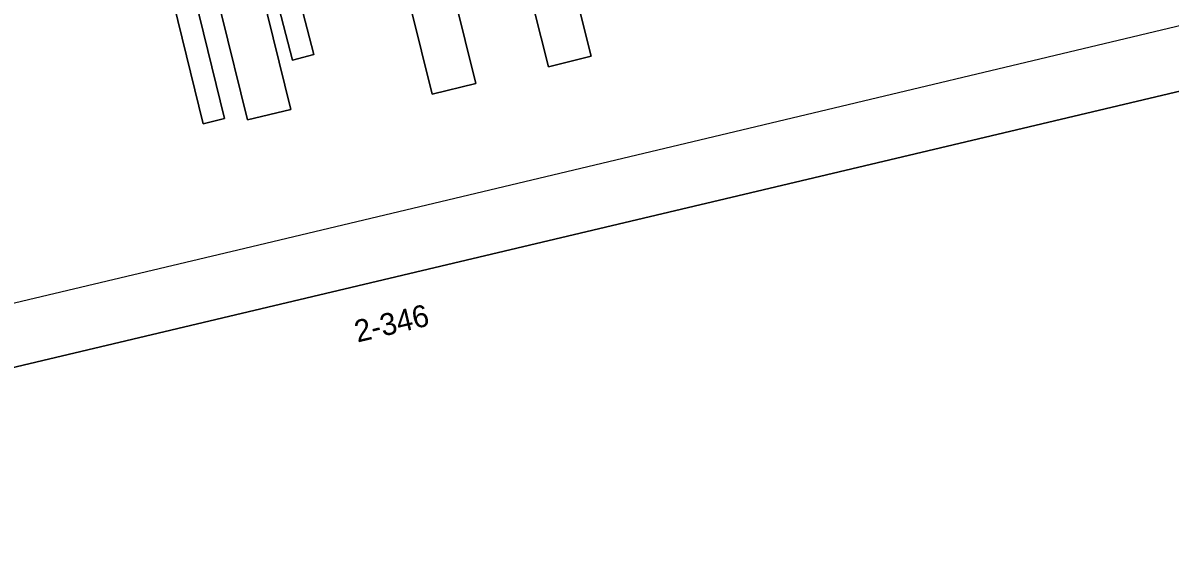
# Model space of a CAD drawing. Extents: x 160675 to 161153, y 383241 to 383714.
# Drawn here: x 161053 to 161105.1, y 383500.1 to 383524.5 of the extents above; entities that cross this region are included whole.
import ezdxf

# ---------------------------------------------------------------- set-up
doc = ezdxf.new("R2010")
doc.units = 0
for name, color, linetype in [('IMGEO_Erf', 7, 'Continuous'), ('IMGEO_Grasland_overig', 7, 'Continuous'), ('IMGEO_Lijnafwatering', 7, 'Continuous'), ('IMGEO_Pand', 7, 'Continuous'), ('IMGEO_Pand_nummerreeks', 7, 'Continuous')]:
    doc.layers.add(name, color=color, linetype=linetype)

msp = doc.modelspace()

# ---------------------------------------------------------------- linework, layer by layer
at = {"layer": 'IMGEO_Erf'}
msp.add_lwpolyline([(161052.435, 383508.826), (161071.419, 383513.322), (161096.427, 383519.245), (161115.421, 383523.744), (161114.881, 383526.021), (161118.321, 383526.837), (161118.855, 383524.59), (161119.003, 383524.618), (161125.936, 383522.583), (161129.509, 383518.779), (161130.837, 383517.366), (161132.472, 383510.337), (161132.436, 383510.213), (161134.678, 383509.541), (161134.952, 383509.459), (161135.314, 383510.8), (161135.177, 383510.84), (161138.899, 383525.073), (161137.716, 383525.208), (161139.225, 383535.866), (161137.381, 383536.146), (161135.039, 383536.433), (161132.522, 383536.943)], dxfattribs=at)
for points in [[(161065.248, 383522.826), (161062.478, 383533.507), (161063.45, 383533.759), (161066.219, 383523.078)], [(161076.883, 383522.511), (161074.916, 383530.322), (161076.86, 383530.811), (161078.827, 383523.001)], [(161065.168, 383520.586), (161063.202, 383520.103), (161060.818, 383529.82), (161062.785, 383530.302)], [(161073.573, 383521.766), (161071.594, 383521.276), (161069.672, 383529.042), (161071.651, 383529.532)], [(161061.196, 383519.927), (161059.283, 383527.732), (161060.25, 383527.969), (161062.162, 383520.164)]]:
    msp.add_lwpolyline(points, close=True, dxfattribs=at)
at = {"layer": 'IMGEO_Grasland_overig'}
for points in [[(161066.219, 383523.078), (161063.45, 383533.759), (161062.478, 383533.507), (161065.248, 383522.826)], [(161078.827, 383523.001), (161076.86, 383530.811), (161074.916, 383530.322), (161076.883, 383522.511)], [(161062.785, 383530.302), (161060.818, 383529.82), (161063.202, 383520.103), (161065.168, 383520.586)], [(161071.651, 383529.532), (161069.672, 383529.042), (161071.594, 383521.276), (161073.573, 383521.766)], [(161062.162, 383520.164), (161060.25, 383527.969), (161059.283, 383527.732), (161061.196, 383519.927)]]:
    msp.add_lwpolyline(points, close=True, dxfattribs=at)
at = {"layer": 'IMGEO_Lijnafwatering'}
for points in [[(161106.017, 383524.483), (161084.388, 383519.34)], [(161084.388, 383519.34), (161062.759, 383514.197)], [(161062.759, 383514.197), (161045.187, 383510.019), (161044.231, 383514.079)]]:
    msp.add_lwpolyline(points, dxfattribs=at)
at = {"layer": 'IMGEO_Pand'}
msp.add_lwpolyline([(161127.242, 383493.025), (161131.445, 383506.803), (161133.658, 383506.139), (161134.678, 383509.541), (161132.436, 383510.213), (161132.472, 383510.337), (161130.837, 383517.366), (161129.509, 383518.779), (161125.936, 383522.583), (161119.003, 383524.618), (161118.855, 383524.59), (161118.321, 383526.837), (161114.881, 383526.021), (161115.421, 383523.744), (161096.427, 383519.245), (161071.419, 383513.322), (161052.435, 383508.826)], dxfattribs=at)

# ---------------------------------------------------------------- texts
at = {"layer": 'IMGEO_Pand_nummerreeks'}
msp.add_text('2-346', height=1, rotation=13.3213, dxfattribs=at).set_placement((161068.2, 383509.991))

doc.saveas('drawing.dxf')
